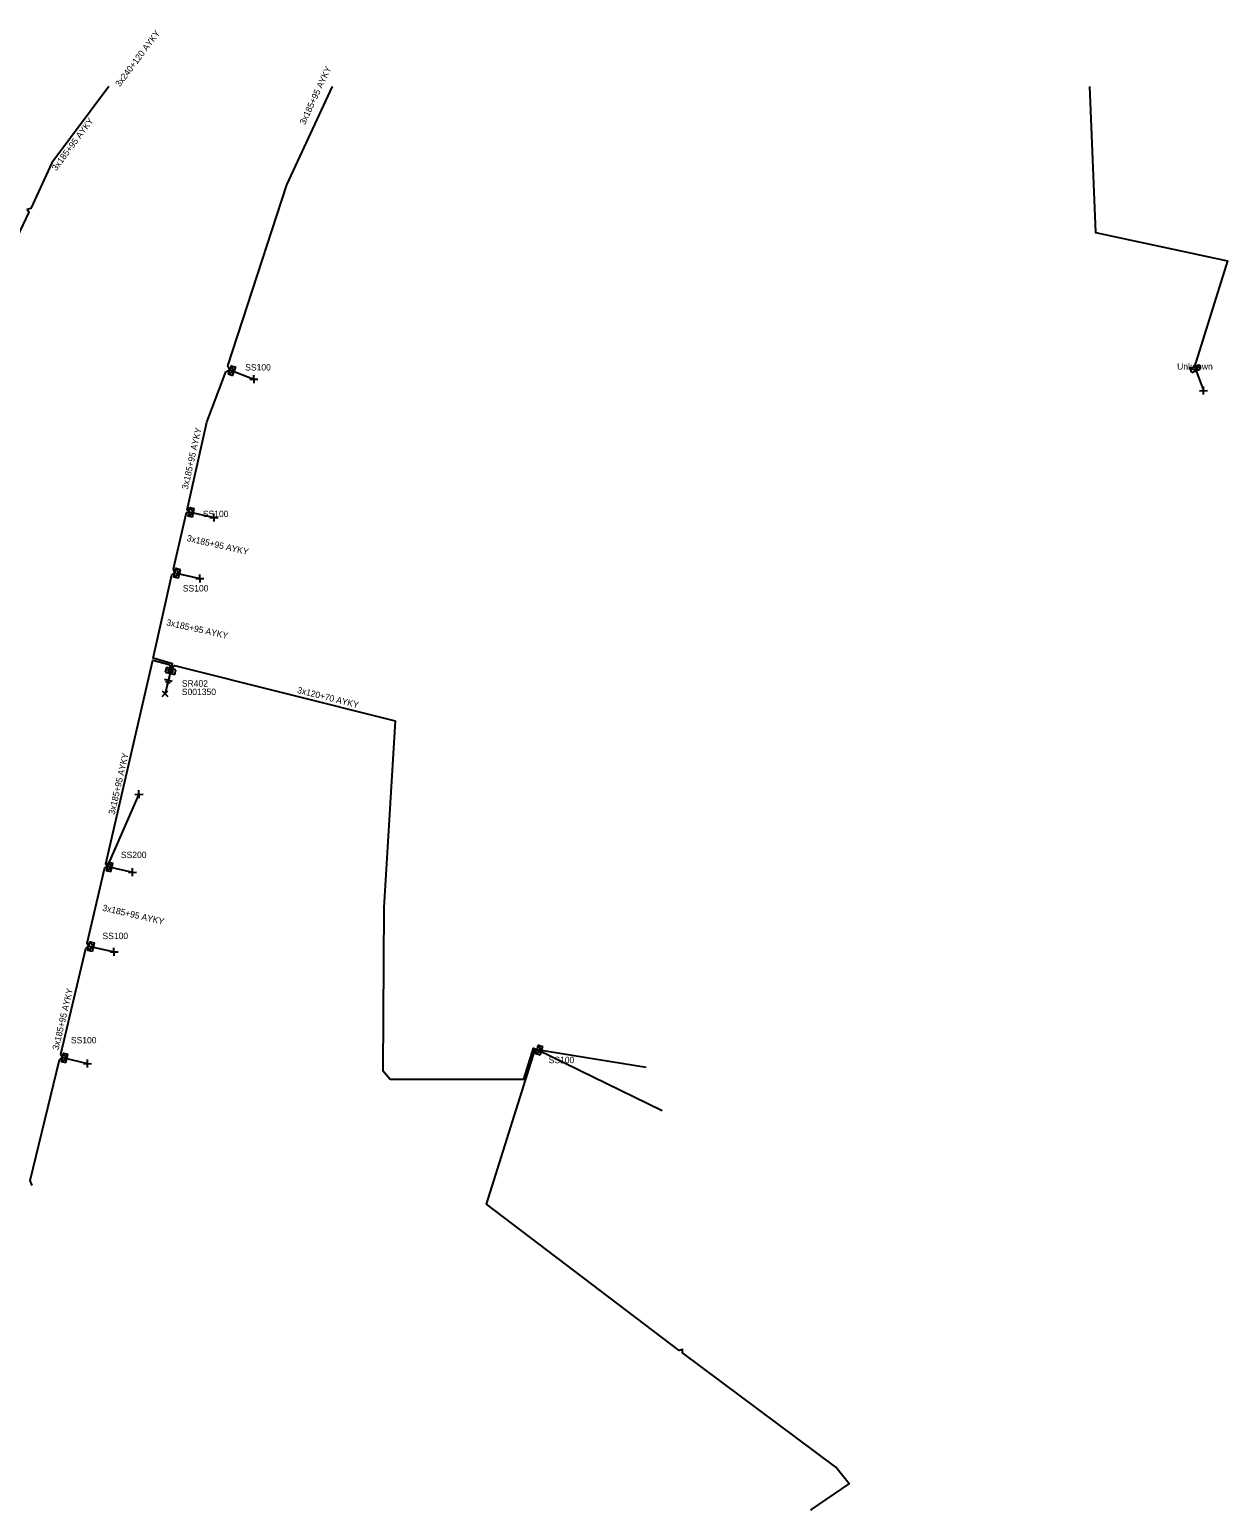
# Model space of a CAD drawing. Extents: x -762284 to -761419, y -1155250 to -1154991.
# Drawn here: x -762078.9 to -761892.4, y -1155221.8 to -1154991.1 of the extents above; entities that cross this region are included whole.
import ezdxf

# ---------------------------------------------------------------- set-up
doc = ezdxf.new("R2010")
doc.units = 0
for name, color, linetype in [('Vrstva 15', 7, 'Continuous'), ('Vrstva 28', 7, 'Continuous'), ('Vrstva 29', 7, 'Continuous'), ('Vrstva 30', 7, 'Continuous'), ('Vrstva 31', 7, 'Continuous'), ('Vrstva 33', 7, 'Continuous'), ('Vrstva 34', 7, 'Continuous'), ('Vrstva 5', 7, 'Continuous'), ('Vrstva 59', 7, 'Continuous'), ('Vrstva 6', 7, 'Continuous')]:
    doc.layers.add(name, color=color, linetype=linetype)

msp = doc.modelspace()

# ---------------------------------------------------------------- linework, layer by layer
at = {"layer": 'Vrstva 15'}
for points in [[(-762056.681, -1155092.664), (-762057.899, -1155092.382)], [(-762056.986, -1155092.912), (-762057.753, -1155092.734)], [(-762057.431, -1155093.132), (-762057.556, -1155093.103)], [(-762057.302, -1155093.162), (-762057.431, -1155093.132)], [(-762057.009, -1155091.305), (-762057.29, -1155092.523)]]:
    msp.add_lwpolyline(points, dxfattribs=at)
at = {"layer": 'Vrstva 28'}
for points in [[(-762057.598, -1155090.509), (-762057.767, -1155091.239)], [(-762056.137, -1155090.846), (-762057.598, -1155090.509)], [(-762057.277, -1155090.771), (-762057.362, -1155091.139)], [(-762057.362, -1155091.139), (-762056.637, -1155091.306)], [(-762057.242, -1155090.827), (-762057.305, -1155091.104)], [(-762057.305, -1155091.104), (-762056.672, -1155091.25)], [(-762056.552, -1155090.938), (-762057.277, -1155090.771)], [(-762057.206, -1155090.884), (-762057.249, -1155091.068)], [(-762057.249, -1155091.068), (-762056.708, -1155091.193)], [(-762056.609, -1155090.974), (-762057.242, -1155090.827)], [(-762056.665, -1155091.009), (-762057.206, -1155090.884)], [(-762057.171, -1155090.941), (-762057.192, -1155091.033)], [(-762057.192, -1155091.033), (-762056.743, -1155091.136)], [(-762056.722, -1155091.044), (-762057.171, -1155090.941)], [(-762057.141, -1155090.996), (-762056.773, -1155091.081)], [(-762056.743, -1155091.136), (-762056.722, -1155091.044)], [(-762056.708, -1155091.193), (-762056.665, -1155091.009)], [(-762056.672, -1155091.25), (-762056.609, -1155090.974)], [(-762056.637, -1155091.306), (-762056.552, -1155090.938)], [(-762056.306, -1155091.577), (-762056.137, -1155090.846)], [(-762057.767, -1155091.239), (-762056.306, -1155091.577)]]:
    msp.add_lwpolyline(points, dxfattribs=at)
at = {"layer": 'Vrstva 31'}
for points in [[(-762047.288, -1155045.047), (-762047.942, -1155044.796), (-762047.44, -1155043.489), (-762046.787, -1155043.74)], [(-762047.037, -1155044.394), (-762047.942, -1155044.796)], [(-762047.037, -1155044.394), (-762047.44, -1155043.489)], [(-762047.288, -1155045.047), (-762046.787, -1155043.74)], [(-761897.885, -1155044.526), (-761898.136, -1155043.872), (-761896.829, -1155043.37), (-761896.578, -1155044.024)], [(-761897.232, -1155044.275), (-761898.136, -1155043.872)], [(-761897.885, -1155044.526), (-761896.578, -1155044.024)], [(-761897.232, -1155044.275), (-761896.829, -1155043.37)], [(-762053.541, -1155067.083), (-762054.226, -1155066.938), (-762053.935, -1155065.568), (-762053.25, -1155065.714)], [(-762053.396, -1155066.398), (-762053.935, -1155065.568)], [(-762053.541, -1155067.083), (-762053.25, -1155065.714)], [(-762053.396, -1155066.398), (-762054.226, -1155066.938)], [(-762055.735, -1155076.573), (-762056.417, -1155076.415), (-762056.102, -1155075.051), (-762055.42, -1155075.209)], [(-762055.578, -1155075.891), (-762056.102, -1155075.051)], [(-762055.578, -1155075.891), (-762056.417, -1155076.415)], [(-762055.735, -1155076.573), (-762055.42, -1155075.209)], [(-762066.241, -1155122.333), (-762066.926, -1155122.187), (-762066.635, -1155120.818), (-762065.95, -1155120.964)], [(-762066.095, -1155121.648), (-762066.635, -1155120.818)], [(-762066.241, -1155122.333), (-762065.95, -1155120.964)], [(-762066.095, -1155121.648), (-762066.926, -1155122.187)], [(-762069.126, -1155134.722), (-762069.808, -1155134.565), (-762069.493, -1155133.201), (-762068.811, -1155133.358)], [(-762068.968, -1155134.04), (-762069.808, -1155134.565)], [(-762068.968, -1155134.04), (-762069.493, -1155133.201)], [(-762069.126, -1155134.722), (-762068.811, -1155133.358)], [(-762073.236, -1155152.092), (-762073.918, -1155151.935), (-762073.603, -1155150.571), (-762072.921, -1155150.728)], [(-762073.079, -1155151.41), (-762073.603, -1155150.571)], [(-762073.236, -1155152.092), (-762072.921, -1155150.728)], [(-761999.396, -1155150.847), (-762000.065, -1155150.642), (-761999.656, -1155149.303), (-761998.986, -1155149.508)], [(-761999.191, -1155150.178), (-762000.065, -1155150.642)], [(-761999.191, -1155150.178), (-761999.656, -1155149.303)], [(-761999.396, -1155150.847), (-761998.986, -1155149.508)], [(-762073.079, -1155151.41), (-762073.918, -1155151.935)]]:
    msp.add_lwpolyline(points, dxfattribs=at)
at = {"layer": 'Vrstva 34'}
for points in [[(-762043.949, -1155046.205), (-762043.971, -1155044.955)], [(-762044.585, -1155045.591), (-762043.335, -1155045.569)], [(-761896.705, -1155047.381), (-761895.455, -1155047.359)], [(-761896.069, -1155047.995), (-761896.091, -1155046.745)], [(-762050.805, -1155067.161), (-762049.555, -1155067.139)], [(-762050.169, -1155067.775), (-762050.191, -1155066.525)], [(-762052.995, -1155076.651), (-762051.745, -1155076.629)], [(-762052.359, -1155077.265), (-762052.381, -1155076.015)], [(-762058.252, -1155094.128), (-762057.368, -1155095.012)], [(-762058.252, -1155095.012), (-762057.368, -1155094.128)], [(-762061.849, -1155110.865), (-762061.871, -1155109.615)], [(-762062.485, -1155110.251), (-762061.235, -1155110.229)], [(-762063.505, -1155122.401), (-762062.255, -1155122.379)], [(-762062.869, -1155123.015), (-762062.891, -1155121.765)], [(-762066.375, -1155134.801), (-762065.125, -1155134.779)], [(-762065.739, -1155135.415), (-762065.761, -1155134.165)], [(-762070.495, -1155152.201), (-762069.245, -1155152.179)], [(-762069.859, -1155152.815), (-762069.881, -1155151.565)]]:
    msp.add_lwpolyline(points, dxfattribs=at)
at = {"layer": 'Vrstva 5'}
for points in [[(-762066.55, -1155000), (-762075.43, -1155011.9), (-762078.71, -1155018.99), (-762079.27, -1155019.15), (-762079.03, -1155019.57), (-762085.78, -1155033.68), (-762086.33, -1155033.77), (-762086.11, -1155034.42), (-762092.35, -1155047.71), (-762097.6, -1155060.59), (-762098.95, -1155063.48), (-762099.32, -1155063.71)], [(-762056.84, -1155090.56), (-762056.67, -1155089.9), (-762059.65, -1155089.06), (-762056.74, -1155076.04), (-762056.26, -1155075.73), (-762056.48, -1155075.12), (-762054.46, -1155066.36), (-762054.08, -1155066.25), (-762054.35, -1155065.92), (-762051.28, -1155052.28), (-762048.34, -1155044.44), (-762047.69, -1155044.14), (-762048.04, -1155043.51), (-762038.86, -1155015.33), (-762031.73, -1155000)], [(-761913.82, -1155000), (-761912.91, -1155022.74), (-761892.36, -1155027.17), (-761897.48, -1155043.62)], [(-762078.49, -1155171.19), (-762078.82, -1155170.4), (-762074.25, -1155151.58), (-762073.76, -1155151.25), (-762074.06, -1155150.74), (-762070.15, -1155134.27), (-762069.65, -1155133.88), (-762069.92, -1155133.43), (-762067.2, -1155121.65), (-762066.78, -1155121.5), (-762067.05, -1155121.07), (-762059.72, -1155089.36), (-762057.14, -1155090.05), (-762056.96, -1155090.53)], [(-762056.71, -1155090.59), (-762056.32, -1155090.2), (-762021.98, -1155098.81), (-762023.73, -1155127.85), (-762023.87, -1155153.28), (-762022.75, -1155154.6), (-762001.95, -1155154.62), (-762000.44, -1155149.76), (-761999.86, -1155149.97)], [(-761957.19, -1155221.77), (-761957.12, -1155221.63), (-761951.27, -1155217.65), (-761953.35, -1155215.02), (-761977.23, -1155197.25), (-761977.22, -1155196.69), (-761977.72, -1155196.89), (-762007.72, -1155174.09), (-762000.24, -1155150.17), (-761999.86, -1155149.97)]]:
    msp.add_lwpolyline(points, dxfattribs=at)
at = {"layer": 'Vrstva 59'}
for points in [[(-762047.7, -1155044.14), (-762043.96, -1155045.58)], [(-761897.48, -1155043.62), (-761896.08, -1155047.37)], [(-762054.08, -1155066.25), (-762050.18, -1155067.15)], [(-762056.26, -1155075.73), (-762052.37, -1155076.64)], [(-762057.07, -1155091.54), (-762057.81, -1155094.57)], [(-762066.78, -1155121.5), (-762061.86, -1155110.24)], [(-762066.78, -1155121.5), (-762062.88, -1155122.39)], [(-762069.65, -1155133.88), (-762065.75, -1155134.79)], [(-761999.86, -1155149.97), (-761980.36, -1155159.47)], [(-761999.86, -1155149.97), (-761982.88, -1155152.75)], [(-762073.76, -1155151.25), (-762069.87, -1155152.19)]]:
    msp.add_lwpolyline(points, dxfattribs=at)

# ---------------------------------------------------------------- texts
at = {"layer": 'Vrstva 29'}
msp.add_text('S001350', height=0.9943, dxfattribs=at).set_placement((-762055.19, -1155094.78))
at = {"layer": 'Vrstva 30'}
msp.add_text('SR402', height=0.9943, dxfattribs=at).set_placement((-762055.19, -1155093.48))
at = {"layer": 'Vrstva 33'}
for s, p in [('SS100', (-762045.32, -1155044.24)), ('Unknown', (-761900.18, -1155044.1)), ('SS100', (-762051.92, -1155067.06)), ('SS100', (-762055.04, -1155078.66)), ('SS200', (-762064.68, -1155120.18)), ('SS100', (-762067.55, -1155132.8)), ('SS100', (-762072.47, -1155149.03)), ('SS100', (-761998.06, -1155152.12))]:
    msp.add_text(s, height=0.9943, dxfattribs=at).set_placement(p)
at = {"layer": 'Vrstva 6'}
for s, height, rotation, p in [('3x240+120 AYKY', 0.99429, 53.02724, (-762064.85, -1155000.14)), ('3x185+95 AYKY', 0.99429, 65.05561, (-762036.01, -1155006.05)), ('3x185+95 AYKY', 0.99429, 53.27739, (-762074.74, -1155013.22)), ('3x185+95 AYKY', 0.99429, 77.33642, (-762054.26, -1155062.83)), ('3x185+95 AYKY', 0.99429, 347.01255, (-762054.48, -1155070.78)), ('3x185+95 AYKY', 0.99428, 347.37711, (-762057.67, -1155083.91)), ('3x120+70 AYKY', 0.99429, 345.91979, (-762037.29, -1155094.45)), ('3x185+95 AYKY', 0.99429, 76.98163, (-762065.67, -1155113.48)), ('3x185+95 AYKY', 0.99429, 346.99259, (-762067.63, -1155128.36)), ('3x185+95 AYKY', 0.99428, 76.64625, (-762074.4, -1155150.13))]:
    msp.add_text(s, height=height, rotation=rotation, dxfattribs=at).set_placement(p)

doc.saveas('drawing.dxf')
